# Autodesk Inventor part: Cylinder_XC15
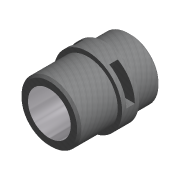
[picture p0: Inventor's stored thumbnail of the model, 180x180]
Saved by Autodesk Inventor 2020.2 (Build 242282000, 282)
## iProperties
Created: 2000-05
Part Number: Cylinder_XC15
Document SubType Name: Modeling
Designer: F.Stasiak
Stock Number: Cylinder_XC15
Density: 1 g/cm^3
Material: Default
Appearance: Aluminium (obrabiane)
Manager: www.cadconsulting.pl
Company: Fabian Stasiak CAD Consulting
Control State: 0
Master: False
Checked Out: False
Shininess: 0.0
Density: 0.0
Volumn: 0.0
Area: 0.0
PropertySet Name: Model Information
Author: F.Stasiak
Subject: Zbiór ćwiczeń. Autodesk Inventor 2020. Kurs podstawowy
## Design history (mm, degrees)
node "Base1"
node "Bryła1"
node "Korpusy bryłowe"
node "Korpusy powierzchniowe"
